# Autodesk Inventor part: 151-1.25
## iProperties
Created: 2007-06
Part Number: 151-1.25
Document SubType Name: Modeling
Designer: btaylor
Density: 1 g/cm^3
Author: btaylor
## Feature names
1. Sweep1
2. Extrusion1
3. Extrusion2
4. Fillet1
5. Fillet2
6. Extrusion3
7. Extrusion4
8. Sweep2
9. Fillet3
10. Fillet4
11. Chamfer1
12. Chamfer2
13. Fillet5
14. Fillet6
